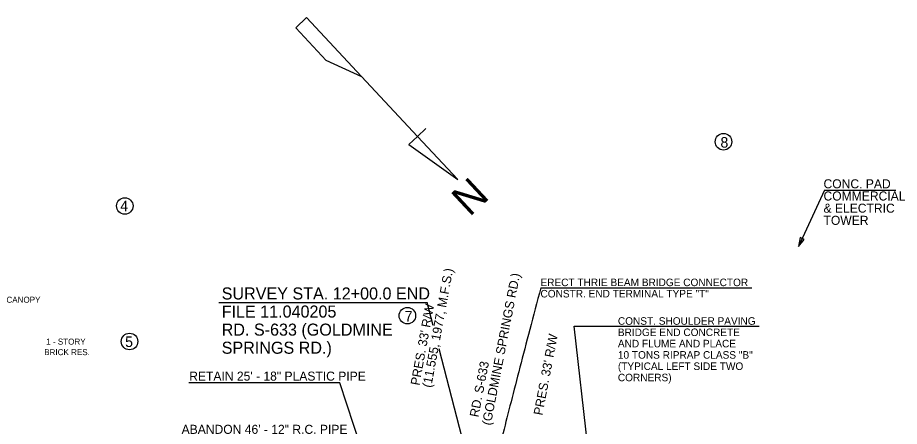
# Model space of a CAD drawing. Extents: x 16382402 to 16388022, y 46194326 to 46202918.
# Drawn here: x 16384585 to 16385170, y 46195221 to 46195492 of the extents above; entities that cross this region are included whole.
import ezdxf

# ---------------------------------------------------------------- set-up
doc = ezdxf.new("R2010")
doc.units = 0
for name, color, linetype in [('RD_EX_DV_Prop', 7, 'Continuous'), ('RD_EX_GuardRail', 7, 'Continuous'), ('RD_EX_Misc', 7, 'Continuous'), ('RD_EX_RW_TX', 7, 'Continuous'), ('RD_PD_ALT2_TX', 7, 'Continuous'), ('RD_PD_Final_TX', 7, 'Continuous'), ('RD_TX_Bldg', 7, 'Continuous'), ('RD_TX_Drainage', 7, 'Continuous'), ('RD_TX_RoadID', 7, 'Continuous')]:
    doc.layers.add(name, color=color, linetype=linetype)

msp = doc.modelspace()

# ---------------------------------------------------------------- linework, layer by layer
at = {"layer": 'RD_EX_DV_Prop'}
for centre in [(16385053.43, 46195409.48), (16384656.11, 46195366.89), (16384843.64, 46195294.08), (16384659.26, 46195276.97)]:
    msp.add_circle(centre, 5.49, dxfattribs=at)
at = {"layer": 'RD_EX_GuardRail'}
for q in [(16385103.2, 46195339.95), (16385167.83, 46195377.47)]:
    msp.add_line((16385120.4, 46195377.47), q, dxfattribs=at)
at = {"layer": 'RD_EX_Misc'}
for p, q in [((16384776.7, 46195491.84), (16384769.53, 46195485.15)), ((16384813.14, 46195452.8), (16384776.7, 46195491.84)), ((16384769.53, 46195485.15), (16384789.78, 46195463.46)), ((16384789.6, 46195463.66), (16384813.14, 46195452.8)), ((16384789.78, 46195463.46), (16384789.6, 46195463.66)), ((16384813.14, 46195452.8), (16384850.26, 46195413.04)), ((16384855.99, 46195418.39), (16384850.26, 46195413.04)), ((16384850.26, 46195413.04), (16384844.53, 46195407.69)), ((16384877.01, 46195384.38), (16384850.26, 46195413.04)), ((16384844.53, 46195407.69), (16384844.85, 46195407.35)), ((16384844.53, 46195407.69), (16384877.01, 46195384.38)), ((16384877.01, 46195384.38), (16384877.01, 46195384.38))]:
    msp.add_line(p, q, dxfattribs=at)
at = {"layer": 'RD_PD_ALT2_TX'}
for p, q in [((16384932.16, 46195312.48), (16385072.26, 46195312.48)), ((16384954.22, 46195287.09), (16385077.13, 46195287.09)), ((16384969.52, 46195152.88), (16384954.22, 46195287.09))]:
    msp.add_line(p, q, dxfattribs=at)
msp.add_open_spline([(16384932.16, 46195312.48), (16384906.33, 46195215.29), (16384886.28, 46195127.34), (16384875.49, 46195071.8), (16384878.11, 46195063.52)], degree=2, dxfattribs=at)
at = {"layer": 'RD_PD_Final_TX'}
for p, q in [((16384718.6, 46195302.83), (16384856.83, 46195302.83)), ((16384860.79, 46195287.54), (16384856.83, 46195302.83)), ((16384885.5, 46195192.3), (16384864.8, 46195272.09))]:
    msp.add_line(p, q, dxfattribs=at)
at = {"layer": 'RD_TX_Drainage'}
for p, q in [((16384798.86, 46195249.48), (16384698.62, 46195249.48)), ((16384829.51, 46195156.34), (16384798.86, 46195249.48))]:
    msp.add_line(p, q, dxfattribs=at)
msp.add_lwpolyline([(16385104.2, 46195345.86), (16385103.2, 46195339.95), (16385107.03, 46195344.57)], close=True, dxfattribs=at)

# ---------------------------------------------------------------- texts
at = {"layer": 'RD_EX_DV_Prop'}
for s, p in [('8', (16385051.41, 46195405.59)), ('4', (16384653.09, 46195363.41)), ('7', (16384841.85, 46195290.22)), ('5', (16384656.32, 46195273.3))]:
    msp.add_text(s, height=7, dxfattribs=at).set_placement(p)
at = {"layer": 'RD_EX_GuardRail'}
for s, p in [('CONC. PAD', (16385119.8, 46195378.59)), ('COMMERCIAL ', (16385119.8, 46195370.51)), ('& ELECTRIC', (16385119.8, 46195362.43)), ('TOWER', (16385119.8, 46195354.35))]:
    msp.add_text(s, height=6, dxfattribs=at).set_placement(p)
at = {"layer": 'RD_EX_Misc'}
msp.add_text('N', height=20, rotation=223.03012, dxfattribs=at).set_placement((16384885.31, 46195387.06))
at = {"layer": 'RD_EX_RW_TX'}
for s, rotation, p in [('(11.555, 1977, M.F.S.)', 79.49719, (16384859.44, 46195246.05)), ("PRES. 33' R/W ", 79.49719, (16384851.58, 46195247.51)), ("PRES. 33' R/W ", 79.15715, (16384933.2, 46195227.65))]:
    msp.add_text(s, height=6, rotation=rotation, dxfattribs=at).set_placement(p)
at = {"layer": 'RD_PD_ALT2_TX'}
for s, p in [('ERECT THRIE BEAM BRIDGE CONNECTOR', (16384931.97, 46195313.69)), ('CONSTR. END TERMINAL TYPE "T"', (16384931.97, 46195306.19)), ('CONST. SHOULDER PAVING', (16384983.34, 46195288.07)), ('BRIDGE END CONCRETE', (16384983.34, 46195280.57)), ('AND FLUME AND PLACE ', (16384983.34, 46195273.07)), ('10 TONS RIPRAP CLASS "B"', (16384983.34, 46195265.57)), ('(TYPICAL LEFT SIDE TWO ', (16384983.34, 46195258.07)), ('CORNERS)', (16384983.34, 46195250.57))]:
    msp.add_text(s, height=5, dxfattribs=at).set_placement(p)
at = {"layer": 'RD_PD_Final_TX'}
for s, p in [('SURVEY STA. 12+00.0 END', (16384720.4, 46195304.84)), ('FILE 11.040205', (16384720.4, 46195292.84)), ('RD. S-633 (GOLDMINE ', (16384720.4, 46195280.84)), ('SPRINGS RD.)', (16384720.4, 46195268.84))]:
    msp.add_text(s, height=8, dxfattribs=at).set_placement(p)
at = {"layer": 'RD_TX_Bldg'}
for s, p in [('CANOPY', (16384577.55, 46195302.67)), ('1 - STORY', (16384603.94, 46195274.9)), ('BRICK RES.', (16384602.63, 46195267.9))]:
    msp.add_text(s, height=4, dxfattribs=at).set_placement(p)
at = {"layer": 'RD_TX_Drainage'}
for s, p in [('RETAIN 25\' - 18" PLASTIC PIPE', (16384698.85, 46195250.98)), ('ABANDON 46\' - 12" R.C. PIPE', (16384693.81, 46195215.69))]:
    msp.add_text(s, height=6, dxfattribs=at).set_placement(p)
at = {"layer": 'RD_TX_RoadID'}
for s, p in [('(GOLDMINE SPRINGS RD.)', (16384898.94, 46195221.04)), ('RD. S-633 ', (16384890.76, 46195226.42))]:
    msp.add_text(s, height=6, rotation=79.00546, dxfattribs=at).set_placement(p)

doc.saveas('drawing.dxf')
